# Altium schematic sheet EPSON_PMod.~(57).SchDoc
size A4
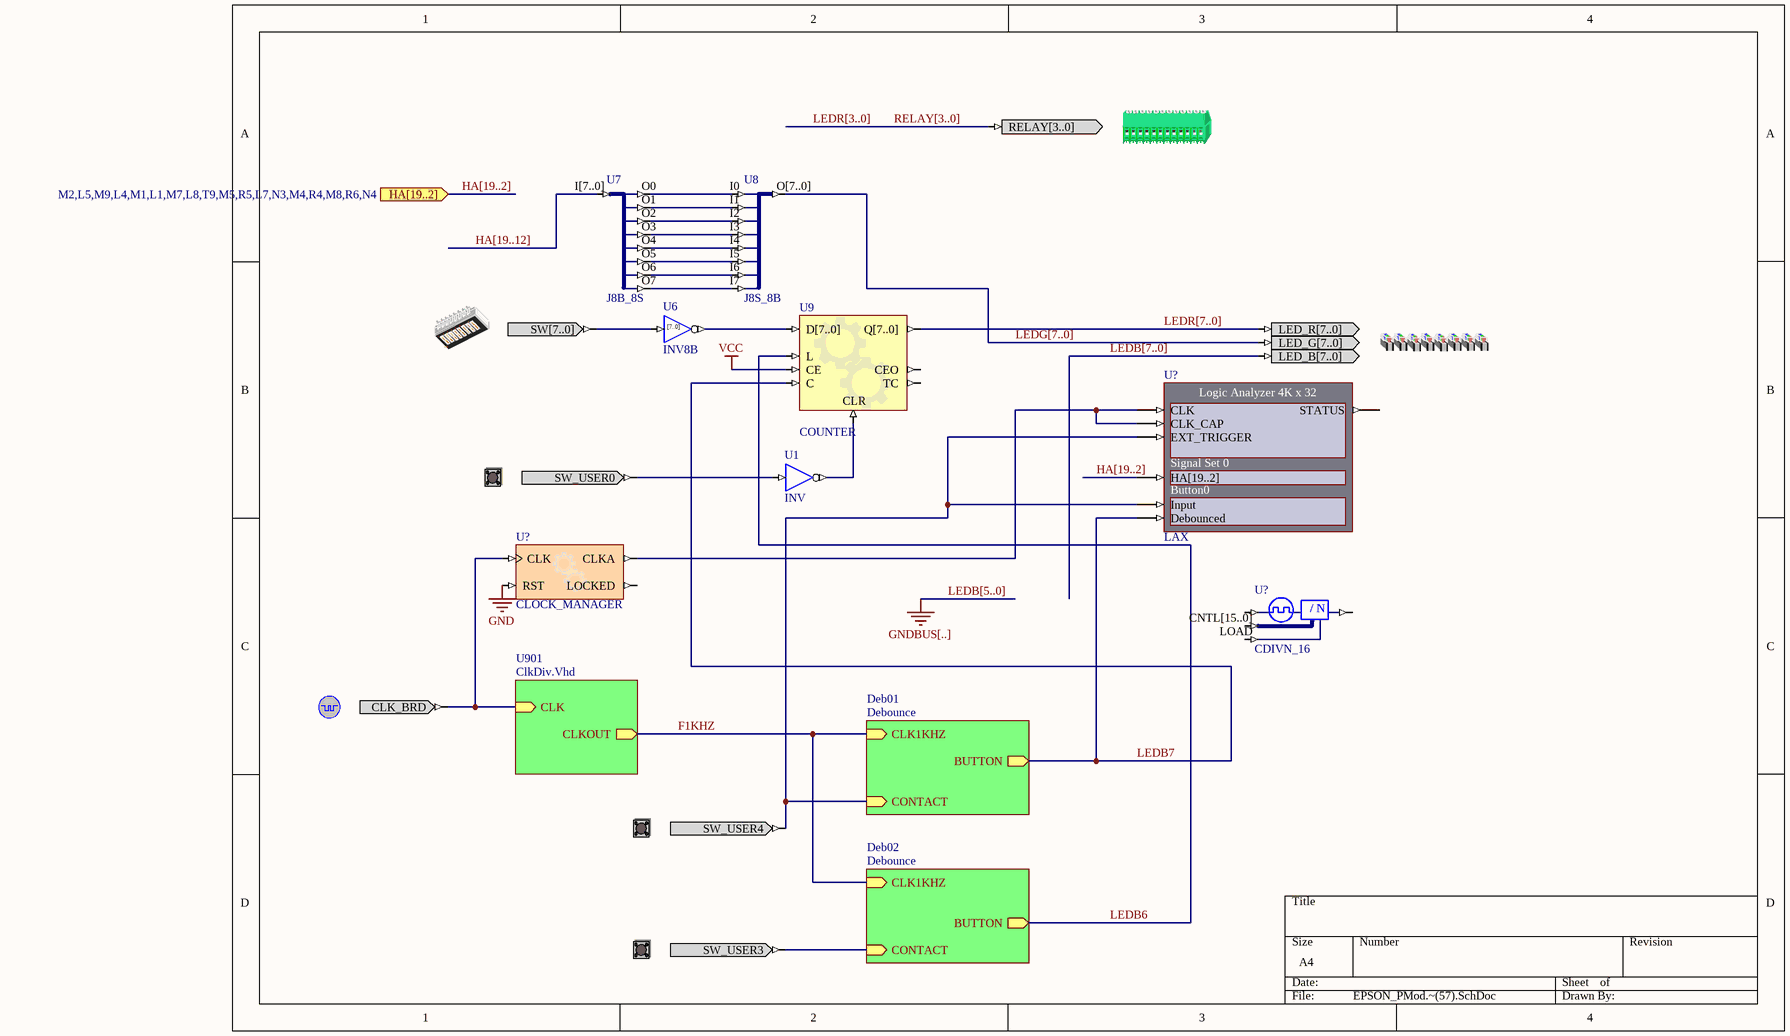
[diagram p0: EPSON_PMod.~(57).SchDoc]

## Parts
(Parts that share a designator on the sheet are numbered #1, #2 ... from top to bottom, then left to right.)
?#1  RELAYCNTR  (value not drawn)
?#2  DIPSWITCH  (value not drawn)
?#3  LEDS_RGB  (value not drawn)
?#4  USER_BUTTON0  (value not drawn)
?#5  CLOCK_BOARD  (value not drawn)
?#6  USER_BUTTON4  (value not drawn)
?#7  USER_BUTTON3  (value not drawn)
U1  INV
U6  INV8B
U7  J8B_8S
U8  J8S_8B
U9  COUNTER
U?#1  LAX
U?#2  CLOCK_MANAGER
U?#3  CDIVN_16

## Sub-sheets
Deb01 = Debounce: CONTACT (in), BUTTON (out), CLK1KHZ (in)
Deb02 = Debounce: CONTACT (in), BUTTON (out), CLK1KHZ (in)
U901 = ClkDiv.Vhd: CLK (in), CLKOUT (out)

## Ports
HA[19..2] (in, see M2,L5,M9,L4,M1,L1,M7,L8,T9,M5,R5,L7,N3,M4,R4,M8,R6,N4)

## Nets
GND: U?#2.RST
GND_BUS[13..0]: U?#1.Set0_Spare[13..0]
GND_BUS[29..0]: U?#1.Set1_Spare[29..0]
VCC: U9.CE
F1KHZ: sheet U901/CLKOUT, sheet Deb01/CLK1KHZ, sheet Deb02/CLK1KHZ
LEDB6: U9.L ; sheet Deb02/BUTTON
LEDB7: U9.C U?#1.Debounced ; sheet Deb01/BUTTON
Net?#4_SW_USER0: ?#4.SW_USER0 U1.I
Net?#5_CLK_BRD: ?#5.CLK_BRD U?#2.CLK ; sheet U901/CLK
Net?#6_SW_USER4: ?#6.SW_USER4 U?#1.EXT_TRIGGER U?#1.Input ; sheet Deb01/CONTACT
Net?#7_SW_USER3: ?#7.SW_USER3 ; sheet Deb02/CONTACT
NetU1_O: U1.O U9.CLR
NetU7_O0: U7.O0 U8.I0
NetU7_O1: U7.O1 U8.I1
NetU7_O2: U7.O2 U8.I2
NetU7_O3: U7.O3 U8.I3
NetU7_O4: U7.O4 U8.I4
NetU7_O5: U7.O5 U8.I5
NetU7_O6: U7.O6 U8.I6
NetU7_O7: U7.O7 U8.I7
NetU?#1_CLK: U?#1.CLK U?#1.CLK_CAP U?#2.CLKA

Not connected (* = marked no-connect by the designer): ?#1 RELAY[3..0]; ?#2 SW[7..0]; ?#3 LED_B[7..0] LED_G[7..0] LED_R[7..0]; U6 I[7..0] O[7..0]; U7 I[7..0]; U8 O[7..0]; U9 CEO D[7..0] Q[7..0] TC; U?#1 HA[19..2] STATUS; U?#2 LOCKED; U?#3 CLKDV CLKIN CNTL[15..0] LOAD

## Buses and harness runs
bus HA[19..2]
bus HA[19..2] = port HA[19..2]
bus HA[19..12]
bus LEDB[5..0]
bus LEDB[7..0]
bus LEDG[7..0]
bus LEDR[3..0] = RELAY[3..0]
bus LEDR[7..0]

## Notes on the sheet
- Labels drawn without touching a wire or pin: GNDBUS[..]

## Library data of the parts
?#1 = RELAYCNTR: RELAY; PortComponent: True
?#2 = DIPSWITCH: 8-Way Dip-Switch; PortComponent: True
?#3 = LEDS_RGB: LEDS RGB; PortComponent: True
?#4 = USER_BUTTON0: Generic User Button; PortComponent: True
?#5 = CLOCK_BOARD: Global System Clock Supply; PortComponent: True
?#6 = USER_BUTTON4: Generic User Button; PortComponent: True
?#7 = USER_BUTTON3: Generic User Button; PortComponent: True
U1 = INV: Inverter; FunctionalClass: Logic Primitive; ArchiveName: GENERIC; VHDLIB_SIM: GENERIC_LIB
U6 = INV8B: 8-Bit Inverter, Bus Version; XilinxEquivalent: INV8; FunctionalClass: Logic Primitive; SubClass: INV; PortSize: 8; ArchiveName: GENERIC; VHDLIB_SIM: GENERIC_LIB
U7 = J8B_8S: 8-Bit input bus to 8 single pin outputs; FunctionalClass: Bus Joiner; PortSize: 8; ArchiveName: GENERIC; VHDLIB_SIM: GENERIC_LIB
U8 = J8S_8B: 8 Single pin inputs to single 8-Bit output bus; FunctionalClass: Bus Joiner; PortSize: 8; ArchiveName: GENERIC; VHDLIB_SIM: GENERIC_LIB
U9 = COUNTER: Configurable Counter; ConfiguratorName: GENERIC_COUNTER; ConfigurationParameters: {}Version[1.0]{}Type[Binary]{}SyncReset[False]{}NegativeClockEdge[False]{}FixedDirection[True]{}IsIncrement[True]{}SignalWidth[8]{}MaxValue[255]{}BusOutput[True]{}Loadable[True]{}BusInput[True]{}
U?#1 = LAX: Configurable Logic Analyzer; NEXUS_CORE: Instrument; NEXUS_JTAG_DEVICE: True; NEXUS_JTAG_ORDER: 0; ConfiguratorName: LogicAnalyser; ConfigurationParameters: {}Version[1.0]{}CaptureWidth[32]{}MemorySize[4K]{}ExtAddrWidth[10]{}Set0[Signal Set 0]{}Set0_Signal0[HA(19..2)]{}Style_Set0_Signal0[Green]{}Set1[Button0]{}Set1_Signal0[Input]{}Style_Set1_Signal0[Default]{}Set1_Signal1[Debounced]{}Style_Set1_Signal1[Default]{}ConnectSpareToGND[True]{}; ChildModel1: LAX_CFG32
U?#2 = CLOCKMANAGER: Configurable Clock Manager; ConfiguratorName: GENERIC_CLOCKMANAGER; ConfigurationParameters: {}Version[1.0]{}Option_Configuration[object TClockManagerPersist / VersionMajor [ 0 / VersionMinor [ 0 / InputFreq [ 50.000000000000000000 / InputName [ 'CLK' / OutputTargets [ < / item / Name [ 'CLKA' / OutFreqMin [ 1.000000000000000000 / OutFreqMax [ 1.000000000000000000 / OutPostDivider [ 1.000000000000000000 / end> / OutputDevices [ < / item / Name [ 'Cyclone3' / Valid [ True / OutputActuals [ < / item / Name [ 'C0' / Multipler [ 32.000000000000000000 / Divider [ 64.000000000000000000 / OutPhase [ 315.000000000000000000 / OutFreq [ 25.000000000000000000 / OutputMap [ 1 / end / item / Name [ 'C1' / Multipler [ 1.000000000000000000 / Divider [ 50.000000000000000000 / OutFreq [ 1.000000000000000000 / OutputMap [ 0 / end / item / Name [ 'C2' / Multipler [ 1.000000000000000000 / Divider [ 1.000000000000000000 / OutFreq [ 50.000000000000000000 / OutputMap [ 2 / end / item / Name [ 'C3' / Multipler [ 1.000000000000000000 / Divider [ 1.000000000000000000 / OutFreq [ 50.000000000000000000 / OutputMap [ 3 / end / item / Name [ 'C4' / Multipler [ 1.000000000000000000 / Divider [ 1.000000000000000000 / OutFreq [ 50.000000000000000000 / OutputMap [ 4 / end> / InternalActuals [ <> / CustomVars [ <> / end> / MinInputFreq [ 5.000000000000000000 / MaxInputFreq [ 473.000000000000000000 / MinOutputFreq [ 0.002000000000000000 / MaxOutputFreq [ 1302.000000000000000000 / MaxOutputCount [ 5 / end]{}
U?#3 = CDIVN_16: 16-Bit Programmable Clock Divider; PortSize: 16; ArchiveName: GENERIC; VHDLIB_SIM: GENERIC_LIB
